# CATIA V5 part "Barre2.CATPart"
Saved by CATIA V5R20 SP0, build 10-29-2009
Part number: Barre2
Publications: "Barre 2", "Pivot2/1", "Pivot2/3"
Bounding box of the stored display mesh (mm): x -56.355 to -0.106, y -6.782 to 50.104, z -5 to 5
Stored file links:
  C:\Users\Admin\Desktop\IAO\Barre2.CATPart
  C:\Users\Admin\Desktop\IAO\Skl_4barres.CATProduct
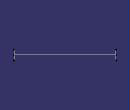
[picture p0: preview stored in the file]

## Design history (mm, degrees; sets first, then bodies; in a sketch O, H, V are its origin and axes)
Set1
  Point1 "Point D": linked copy from another document
  Point2 "Point C": linked copy from another document
  Plane1 "Plan ref": linked copy from another document
Set2
  Line1: type PtPt, FirstPoint Point1, SecondPoint Point2
  Line2: type Normal, RefPoint Point2, RefSkin Plane1, Start -5, End 5
  Line3: type Normal, RefPoint Point1, RefSkin Plane1, Start -5, End 5
Body1 (main body)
